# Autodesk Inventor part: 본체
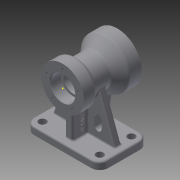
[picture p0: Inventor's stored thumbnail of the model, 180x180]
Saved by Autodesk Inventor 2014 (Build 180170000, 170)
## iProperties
Created: 2015-08
Part Number: 본체
Material: 일반
Document SubType Name: Modeling
Designer: USER
Density: 1 g/cm^3
Appearance: 기본값
Author: USER
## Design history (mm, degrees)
sketch "스케치1"
  geometry: C1 r 26 at (0, 0); 1 further point
  constraints: 1 centre point, 1 coincident
  dimensions: "d1" = 52 diameter of C1
extrude "돌출1" new body sketch "스케치1" distance "d2" = 90; taper "d3" = 0 deg
sketch "스케치2"
  geometry: C1 r 26 at (0, 0) reference; C2 r 35 at (0, 0)
  constraints: 1 centre point, 1 coincident
  dimensions: "d4" = 70 diameter of C2
extrude "돌출2" join sketch "스케치2" distance "d5" = 20; taper "d6" = 0 deg
sketch "스케치3"
  geometry: C1 r 26 at (0, 0) reference; C2 r 40 at (0, 0)
  constraints: 1 centre point, 1 coincident
  dimensions: "d7" = 80 diameter of C2
extrude "돌출3" join sketch "스케치3" distance "d8" = 20; taper "d9" = 0 deg
node "작업축1"
node "작업 평면1"
sketch "스케치5"
  geometry: L1 (20, -35)-(20, 35) reference; L2 (20, 26)-(70, 26) reference; L3 (70, 40)-(70, -40) reference; L4 (20, 35)-(25.196, 26); L5 (70, 40)-(53.315, 26); L6 (25.196, 26)-(20, 26); L7 (20, 35)-(20, 26); L8 (53.315, 26)-(70, 26); L9 (70, 40)-(70, 26); L10 (-18, 0)-(108, 0) reference; 1 further point
  constraints: 12 end point, 3 point on line, 2 perpendicular
revolve "회전1" sketch "스케치5" stored, may be unused: angle "d13" = 90 deg
sketch "스케치6"
  geometry: C1 r 35 at (0, 0) reference; C2 r 20 at (0, 0)
  constraints: 1 centre point, 1 coincident
  dimensions: "d14" = 40 diameter of C2
extrude "돌출4" cut sketch "스케치6" distance "d15" = 17; taper "d16" = 0 deg
sketch "스케치7"
  geometry: C1 r 20 at (0, 0) reference; C2 r 16 at (0, 0)
  constraints: 1 centre point, 1 coincident
  dimensions: "d17" = 32 diameter of C2
extrude "돌출5" cut sketch "스케치7" stored distance "d18" = 17; taper "d19" = 0 deg
sketch "스케치8"
  geometry: C1 r 16 at (0, 0) reference; C2 r 40 at (0, 0) reference; C3 r 26 at (0, 0)
  constraints: 1 centre point, 1 coincident
  dimensions: "d20" = 52 diameter of C3
extrude "돌출6" cut sketch "스케치8" distance "d21" = 20; taper "d22" = 0 deg
sketch "스케치10"
  geometry: 1 further point
hole "구멍1" sketch "스케치10" at (0, 27) diameter "d27" = 3.459; stored, may be unused: countersink angle "d31" = 90 deg, drill point angle "d33" = 118 deg; dims "d28" = 10, "d29" = 4, "d30" = 2, "d32" = 13
sketch "스케치12"
  geometry: 1 further point
hole "구멍2" sketch "스케치12" at (0, -33) diameter "d39" = 3.459; stored, may be unused: countersink angle "d43" = 90 deg, drill point angle "d45" = 118 deg; dims "d40" = 10, "d41" = 4, "d42" = 2, "d44" = 13
node "작업 평면3"
  node "작업 평면2"
sketch "스케치13"
  geometry: L1 (-18, 0)-(108, 0) reference; L2 (80, -61)-(80, 61); L3 (0, 61)-(80, 61); L4 (0, -61)-(80, -61); L5 (0, 61)-(0, -61)
  constraints: 8 end point, 2 parallel, 1 perpendicular
extrude "돌출8" join sketch "스케치13" distance "d54" = 12; taper "d55" = 0 deg
sketch "스케치14"
  geometry: L1 (-61, 80)-(-61, 0) reference; C1 r 6 at (-47, 14); C2 r 6 at (-44.946, 64.554); C3 r 6 at (47, 14); C4 r 6 at (47, 66); 2 further points
  constraints: 4 centre point, 1 midpoint
  dimensions: "d58" = 12 diameter of C1; "d59" = 12 diameter of C2; "d60" = 12 diameter of C3; "d61" = 12 diameter of C4
extrude "돌출9" cut sketch "스케치14" distance "d62" = 12; taper "d63" = 0 deg
sketch "스케치15"
  geometry: L1 (10, -26.328)-(10, -78); L2 (10, -78)-(70, -78); L3 (70, -78)-(77.678, -34.454); L4 (10, -26.328)-(28.42, -21.116); L5 (28.42, -21.116)-(65.452, -21.116); L6 (65.452, -21.116)-(70, -33.1); L7 (70, -33.1)-(77.678, -34.454); 1 further point
  constraints: 14 end point, 2 perpendicular, 1 vertical
extrude "돌출10" join sketch "스케치15" stored distance "d67" = 12; taper "d68" = 0 deg
node "작업 평면4"
sketch "스케치16"
  geometry: L1 (36.897, 85.898)-(10, 12); L2 (0, 0)-(0, 12) reference; L3 (85.103, 85.898)-(112, 12); L4 (10, 4.344)-(112, 4.344); L5 (112, 12)-(112, 4.344); L6 (10, 12)-(10, 4.344); A1 r 24.45 centre (61, 90) between (36.897, 85.898) and (85.103, 85.898); 1 further point
  constraints: 10 end point, 2 point on circle, 1 centre point, 1 coincident, 1 parallel
extrude "돌출11" join sketch "스케치16" stored distance "d71" = 12; taper "d72" = 0 deg
sketch "스케치17"
  geometry: 2 further points
  constraints: 1 other
feature "엠보싱1" sketch "스케치17" dims "d1" = 52, "d75" = 0.5, "d76" = 0
fillet "모깎기1" dims "d77" = 5
fillet "모깎기2" dims "d78" = 3
fillet "모깎기3" dims "d79" = 3
sketch "스케치19"
  geometry: 1 further point
sketch "스케치20"
  geometry: 1 further point
sketch "스케치21"
  geometry: C1 r 16 at (0, 0) reference; C2 r 26 at (0, 0) reference; C3 r 19 at (0, 0)
  constraints: 1 centre point, 1 coincident
  dimensions: "d83" = 38 diameter of C3
extrude "돌출12" cut sketch "스케치21" distance "d84" = 3; taper "d85" = 0 deg
fillet "모깎기4" dims "d86" = 3
fillet "모깎기5" dims "d87" = 14
fillet "모깎기6" dims "d88" = 0.3
fillet "모깎기7" dims "d89" = 3
chamfer "모따기1" distance "d90" = 1; stored, may be unused: second distance "d91" = 2, angle "d92" = 45 deg
fillet "모깎기8" dims "d93" = 3
sketch "스케치22"
  geometry: L1 (107.716, 15)-(70, 15) reference; L2 (61, 90)-(61, -15.174); L3 (91, 42.001)-(91.085, 30); L4 (79.085, 30)-(79, 41.958); A1 r 29 centre (61, 90) between (70, 62.432) and (85.856, 75.06) reference; A2 r 6 centre (85.085, 30) between (79.085, 30) and (91.085, 30.085); A3 r 6 centre (85, 42.001) between (91, 42.001) and (79, 41.958)
  constraints: 6 end point, 5 point on circle, 2 centre point, 1 perpendicular, 1 point on line, 1 tangent
extrude "돌출13" cut sketch "스케치22" stored distance "d100" = 0; taper "d101" = 0 deg
node "솔리드1"
pattern_circular "원형 패턴1" dims angle "d35" = 360 deg
pattern_circular "원형 패턴2" dims angle "d47" = 360 deg
mirror "대칭1"
other parameters: "d10" = 0, "d49" = 0, "d94" = 24
